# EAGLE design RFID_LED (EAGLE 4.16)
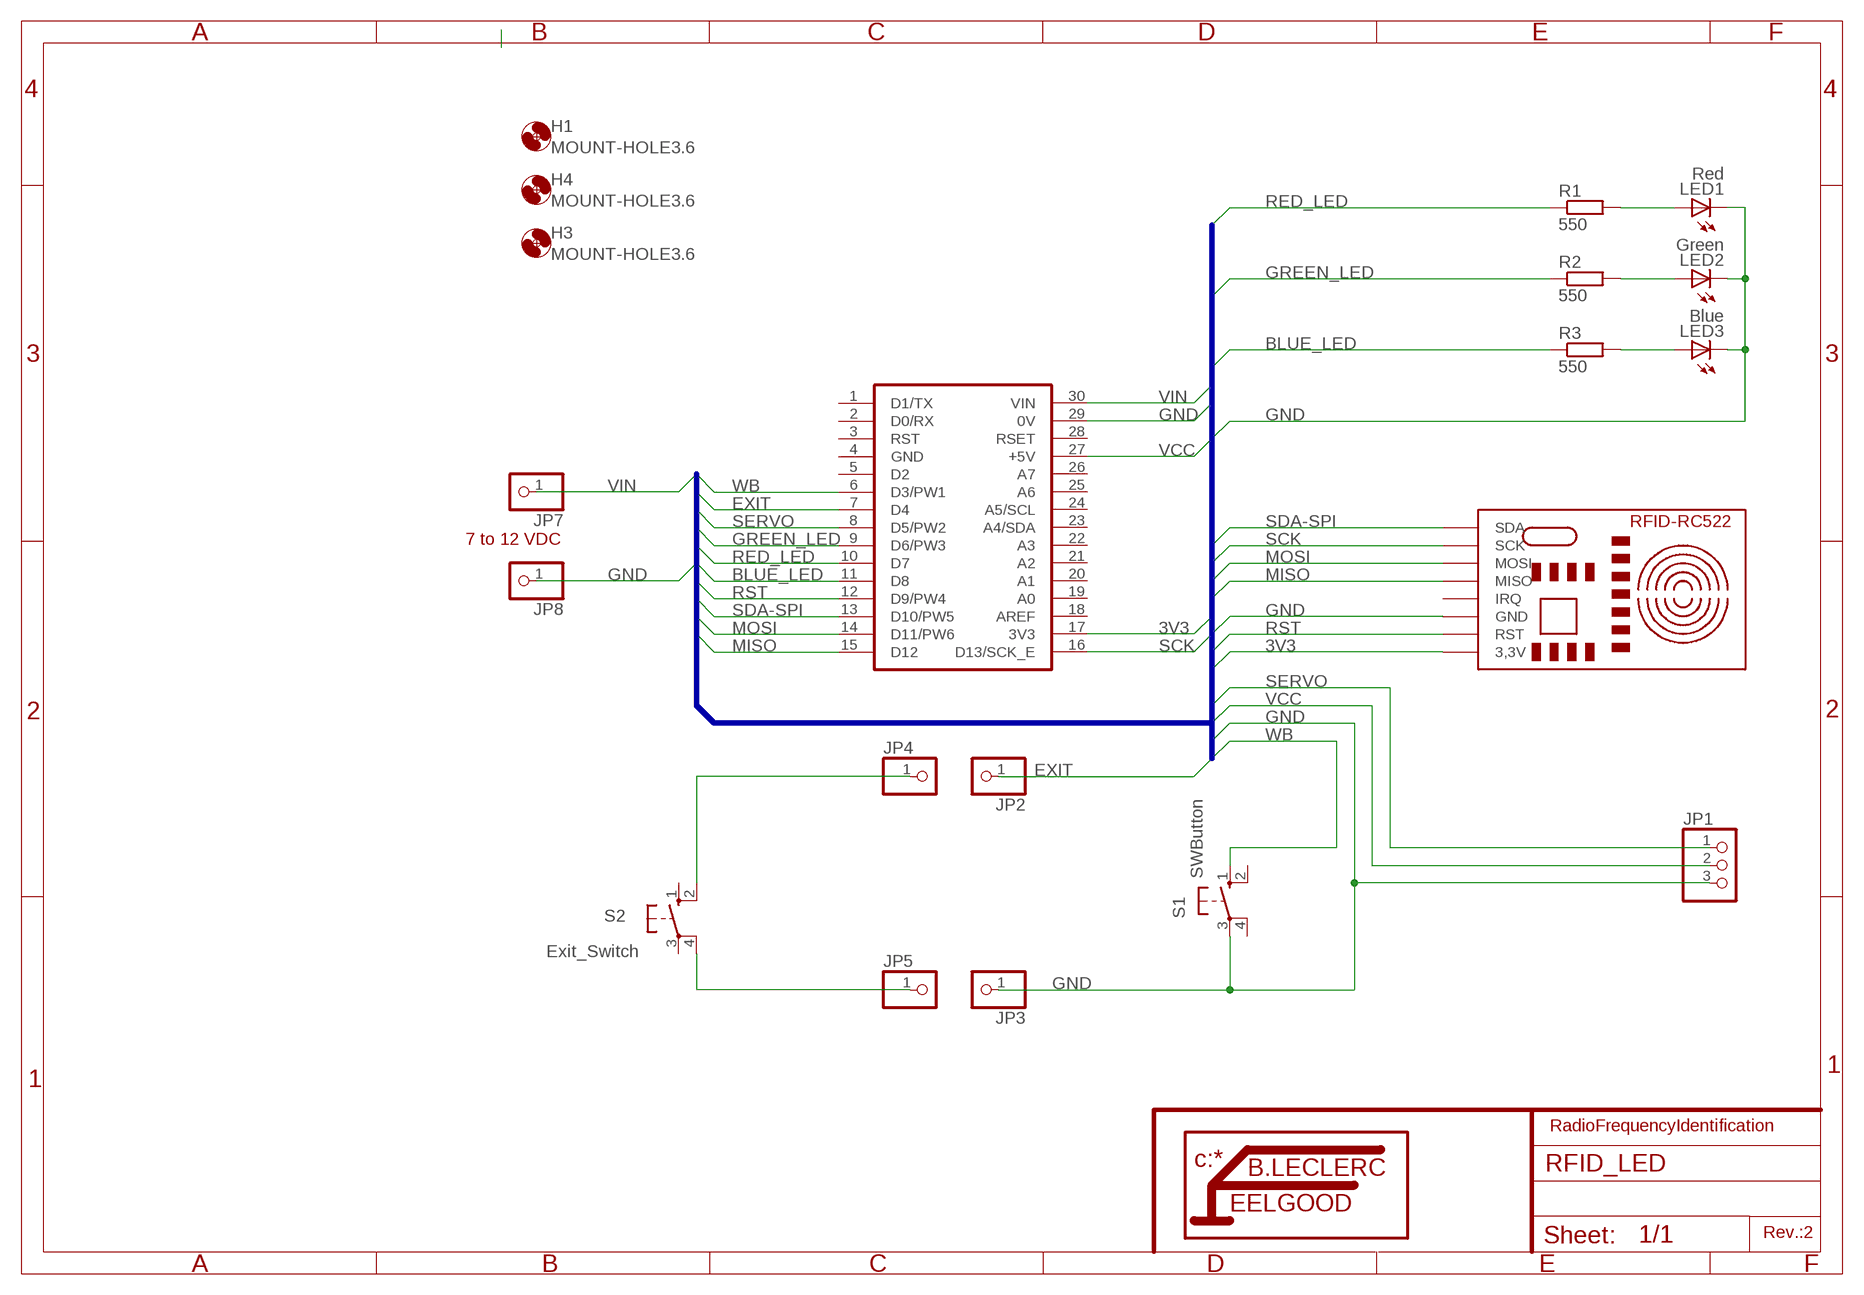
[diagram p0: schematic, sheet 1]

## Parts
H1  MOUNT-HOLE3.6  [3,6]
H3  MOUNT-HOLE3.6  [3,6]
H4  MOUNT-HOLE3.6  [3,6]
JP1  PINHD-1X3  [1X03]
JP2  PINHD-1X1  [1X01]
JP3  PINHD-1X1  [1X01]
JP4  PINHD-1X1  [1X01]
JP5  PINHD-1X1  [1X01]
JP7  PINHD-1X1  [1X01]
JP8  PINHD-1X1  [1X01]
LED1  Red  LED5MM  [LED5MM]
LED2  Green  LED5MM  [LED5MM]
LED3  Blue  LED5MM  [LED5MM]
R1  550  R-EU_M1206  [M1206]
R2  550  R-EU_M1206  [M1206]
R3  550  R-EU_M1206  [M1206]
S1  SWButton  10-XX  [B3F-10XX]
S2  Exit_Switch  10-XX  [B3F-10XX]
U1  NANO  [NANO]
U$3  RFID-RC522  [RFID-RC522]

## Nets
3V3: U1.17(3V3) U$3.3;3V(3,3V)
BLUE_LED: R3.1 U1.11(D8)
EXIT: JP2.1 U1.7(D4)
GND: JP1.3 JP3.1 JP8.1 LED1.K(C) LED2.K(C) LED3.K(C) S1.3(P) U1.29(0V) U$3.GND
GREEN_LED: R2.1 U1.9(D6/PW3)
MISO: U1.15(D12) U$3.MISO
MOSI: U1.14(D11/PW6) U$3.MOSI
N$1: JP5.1 S2.4(P1)
N$3: LED1.A R1.2
N$4: LED2.A R2.2
N$6: LED3.A R3.2
N$8: JP4.1 S2.2(S1)
RED_LED: R1.1 U1.10(D7)
RST: U1.12(D9/PW4) U$3.RST
SCK: U1.16(D13/SCK_E) U$3.SCK
SDA-SPI: U1.13(D10/PW5) U$3.SDA
SERVO: JP1.1 U1.8(D5/PW2)
VCC: JP1.2 U1.27(+5V)
VIN: JP7.1 U1.30(VIN)
WB: S1.1(S) U1.6(D3/PW1)
Unconnected: S1.2(S1) S1.4(P1) S2.1(S) S2.3(P) U1.1(D1/TX) U1.2(D0/RX) U1.3(RST) U1.5(D2) U1.18(AREF) U1.19(A0) U1.20(A1) U1.21(A2) U1.22(A3) U1.23(A4/SDA) U1.24(A5/SCL) U1.25(A6) U1.26(A7) U1.28(RSET) U$3.IRQ

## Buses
B$1

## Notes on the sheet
- 7 to 12 VDC
- RadioFrequencyIdentification
- Rev.:2

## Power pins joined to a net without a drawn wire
GND: U1.4(GND)

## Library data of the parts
H1 H3 H4 = holes:MOUNT-HOLE: MOUNTING HOLE with drill center marker
JP1 = pinhead:PINHD-1X3: PIN HEADER
JP2-JP5 JP7 JP8 = pinhead:PINHD-1X1: PIN HEADER
LED1-LED3 = led:LED: LED
R1-R3 = rcl:R-EU_: RESISTOR, European symbol
S1 S2 = switch-omron:10-XX: OMRON SWITCH
U1 = Arduino:NANO
U$3 = Arduino:RFID-RC522

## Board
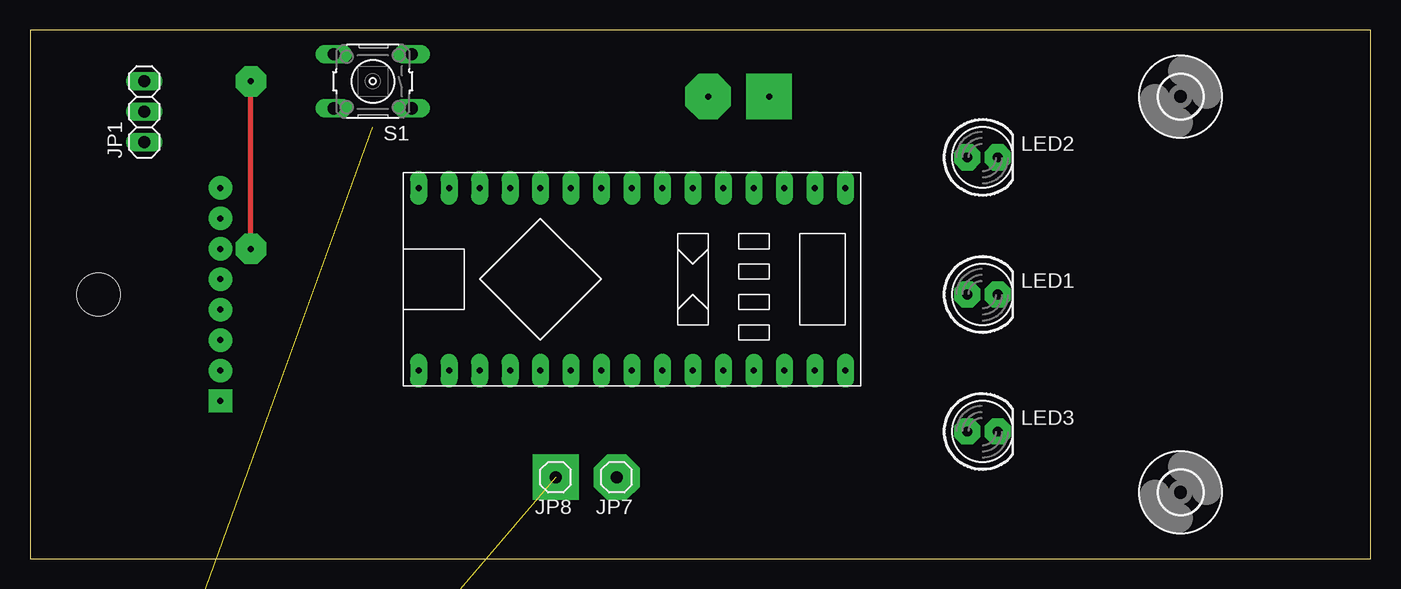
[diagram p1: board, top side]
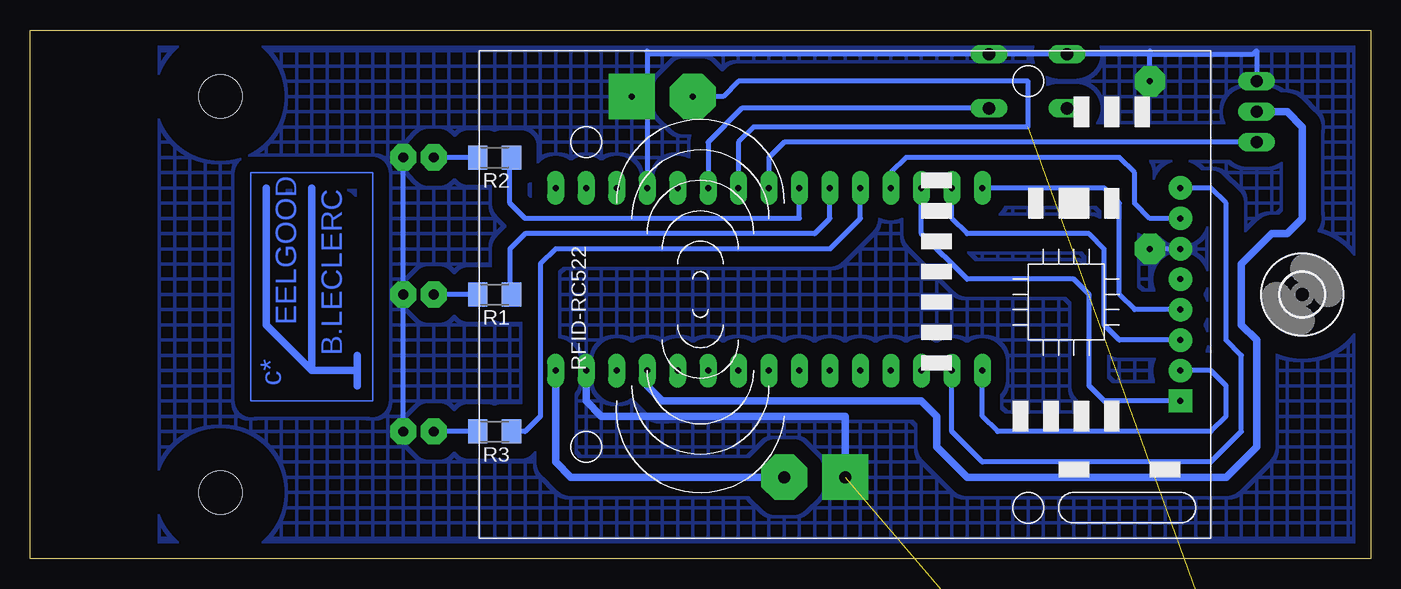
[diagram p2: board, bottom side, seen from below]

Size 111.74 x 44.12 mm. Coordinates in mm from the lower left corner, seen from the top.
Outline: 0,0 111.74,0 111.74,44.12 0,44.12 0,0
Copper layers (1*16): Top 0.035mm / dielectric 1.5mm / Bottom 0.035mm
Design rules "default": minimum track width 10mil, minimum drill 24mil, track to track 8mil, track to pad 8mil, pad to pad 8mil, via to via 8mil, smd to smd 8mil, copper to edge 40mil, drill to drill 8mil, minimum pad ring 10mil, minimum via ring 8mil, stop-mask expansion 4mil, vias tented up to drill 0mil, thermal gap 10mil

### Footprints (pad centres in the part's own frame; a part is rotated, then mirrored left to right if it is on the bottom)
3,6 = hole 3.6: 0,0
1X03 = drill 1.016 long: 1 -2.54,0; 2 0,0; 3 2.54,0
1X01 = drill 1.016 octagon: 1 0,0
LED5MM = drill 0.813 octagon: A -1.27,0; K 1.27,0
M1206 = smd 1.6 x 2: 1 -1.4,0; 2 1.4,0
B3F-10XX = drill 1.016 long: 1 -3.251,2.261; 2 3.251,2.261; 3 -3.251,-2.261; 4 3.251,-2.261
NANO = drill 0.5 pad 1.422 long: 1 -7.62,17.78; 2 -7.62,15.24; 3 -7.62,12.7; 4 -7.62,10.16; 5 -7.62,7.62; 6 -7.62,5.08; 7 -7.62,2.54; 8 -7.62,0; 9 -7.62,-2.54; 10 -7.62,-5.08; 11 -7.62,-7.62; 12 -7.62,-10.16; 13 -7.62,-12.7; 14 -7.62,-15.24; 15 -7.62,-17.78; 16 7.62,-17.78; 17 7.62,-15.24; 18 7.62,-12.7; 19 7.62,-10.16; 20 7.62,-7.62; 21 7.62,-5.08; 22 7.62,-2.54; 23 7.62,0; 24 7.62,2.54; 25 7.62,5.08; 26 7.62,7.62; 27 7.62,10.16; 28 7.62,12.7; 29 7.62,15.24; 30 7.62,17.78
RFID-RC522 = drill 0.5 pad 1.93 round: 3;3V -27.94,-8.89; GND -27.94,-3.81; IRQ -27.94,-1.27; MISO -27.94,1.27; MOSI -27.94,3.81; RST -27.94,-6.35; SCK -27.94,6.35 | drill 0.5 pad 1.93 square: SDA -27.94,8.89

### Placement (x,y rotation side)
H1  95.88,38.57 0 top
H3  95.88,5.55 0 top
H4  5.71,22.06 0 bottom
JP1  9.52,37.3 90 top
JP2  not placed on the board
JP3  not placed on the board
JP4  not placed on the board
JP5  not placed on the board
JP7  48.89,6.82 180 top
JP8  43.81,6.82 180 top
LED1  79.37,22.06 0 top
LED2  79.37,33.49 0 top
LED3  79.37,10.63 0 top
R1  73.02,22.06 180 bottom
R2  73.02,33.49 180 bottom
R3  73.02,10.63 180 bottom
S1  28.57,39.84 180 top
S2  not placed on the board
U1  50.16,23.33 270 top
U$2  [LITTFEEL]  80.64,15.71 90 bottom
U$3  43.81,22.06 180 bottom

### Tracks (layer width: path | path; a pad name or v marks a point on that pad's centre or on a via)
3V3
  Bottom 0.406: U1.17 34.92,10.63 32.38,8.09 13.33,8.09 10.79,10.63 10.79,16.98 12.06,18.25 12.06,29.68 13.33,30.95 U$3.3;3V
BLUE_LED
  Bottom 0.406: U1.11 42.54,28.41 45.08,25.87 67.94,25.87 69.21,24.6 69.21,11.9 70.48,10.63 R3.1 71.75,10.63
EXIT  (via drill 0.5 pad 3.81)  (1 unrouted)
  Bottom 0.406: v56.51,38.57 53.97,38.57 52.7,39.84 28.57,39.84 28.57,36.03 51.43,36.03 52.7,34.76 U1.7
GND  (via drill 0.5 pad 1.27, 0.5 pad 2.18, 0.5 pad 2.54, 0.5 pad 3.81)  (1 unrouted)
  Top 0.406: v18.41,25.87 v18.41,39.84
  Bottom 0.406: U1.4 60.32,42.38 60.04,42.1 S1.3 18.41,42.1 | 18.41,42.1 9.8,42.1 9.52,42.38 JP1.3 | LED2.K LED1.K LED3.K | U$3.GND v18.41,25.87 | 18.41,42.1 18.41,42.38 | v18.41,39.84 18.41,42.1
  Bottom 0.61: U1.29 65.4,13.17 64.13,11.9 43.81,11.9 JP8.1
  other vias: 43.81,6.82 80.64,33.49 80.64,22.06 80.64,10.63 32.06,42.06 9.52,39.84 61.59,38.57
  pour Bottom (isolate 1.27, no thermals, hatched): 0.63,43.65 99.69,43.65 100.96,43.65 100.96,0.47 0.63,0.47
GREEN_LED
  Bottom 0.406: U1.9 47.62,28.41 70.48,28.41 71.75,29.68 71.75,33.49 R2.1
MISO
  Bottom 0.406: U1.15 22.22,30.95 20.95,29.68 20.95,22.06 19.68,20.79 U$3.MISO
MOSI
  Bottom 0.406: U1.14 34.92,28.41 33.65,27.14 23.49,27.14 22.22,25.87 22.22,19.52 20.95,18.25 U$3.MOSI
N$1  (1 unrouted)
N$2  (via drill 0.5 pad 3.81)
  other vias: 48.89,6.82
N$3
  Bottom 0.406: R1.2 LED1.A
N$4
  Bottom 0.406: R2.2 LED2.A
N$5  (via drill 0.5 pad 2.18)
  other vias: 78.1,33.49
N$6
  Bottom 0.406: R3.2 LED3.A
N$7  (via drill 0.5 pad 2.18)
  other vias: 78.1,22.06
N$8  (1 unrouted)
N$9  (via drill 0.5 pad 2.18)
  other vias: 78.1,10.63
N$13  (via drill 0.5 pad 1.27)
  other vias: 9.52,37.3
N$14  (via drill 0.5 pad 1.27)
  other vias: 9.52,34.76
N$16  (via drill 0.5 pad 1.27)
  other vias: 25.08,42.06
N$17  (via drill 0.5 pad 1.27)
  other vias: 25.39,37.62
N$19  (via drill 0.5 pad 1.27)
  other vias: 32.06,37.62
RED_LED
  Bottom 0.406: U1.10 45.08,28.41 46.35,27.14 70.48,27.14 71.75,25.87 71.75,22.06 R1.1
RST
  Bottom 0.406: U1.12 40,32.22 38.73,33.49 20.95,33.49 19.68,32.22 19.68,29.68 18.41,28.41 U$3.RST
SCK
  Bottom 0.406: U1.16 32.38,11.9 31.11,10.63 13.33,10.63 12.06,11.9 12.06,14.44 13.33,15.71 U$3.SCK
SDA-SPI
  Bottom 0.406: U1.13 37.46,27.14 33.65,23.33 24.76,23.33 23.49,22.06 23.49,14.44 22.22,13.17 U$3.SDA
SERVO
  Bottom 0.406: JP1.1 48.89,34.76 50.16,33.49 U1.8
VCC
  Bottom 0.61: JP1.2 6.98,37.3 5.71,36.03 5.71,28.41 6.98,27.14 8.25,27.14 10.79,24.6 10.79,19.52 9.52,18.25 9.52,9.36 12.06,6.82 33.65,6.82 36.19,9.36 36.19,11.9 37.46,13.17 59.05,13.17 60.32,14.44 U1.27
VIN
  Bottom 0.61: U1.30 67.94,8.09 66.67,6.82 JP7.1
WB
  Bottom 0.406: S1.1 52.42,37.58 55.24,34.76 U1.6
